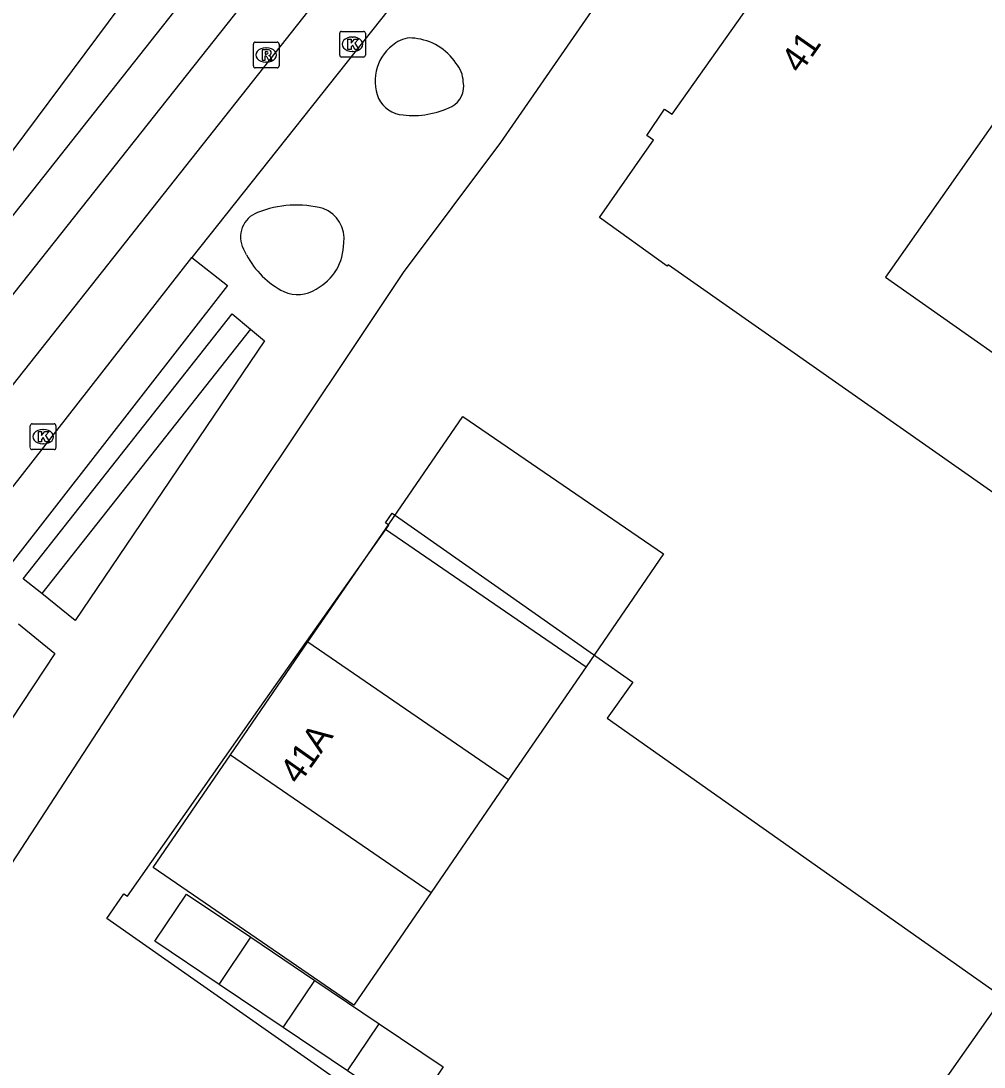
# Model space of a CAD drawing. Extents: x 161355 to 162026, y 386504 to 387459.
# Drawn here: x 161708.95 to 161746.37, y 387026.14 to 387066.79 of the extents above; entities that cross this region are included whole.
import ezdxf

# ---------------------------------------------------------------- set-up
doc = ezdxf.new("R2010")
doc.units = 0
for name, color, linetype in [('IMGEO_Groenvoorziening', 7, 'Continuous'), ('IMGEO_Kolk', 7, 'Continuous'), ('IMGEO_Pand', 7, 'Continuous'), ('IMGEO_Pand_nummerreeks', 7, 'Continuous'), ('IMGEO_Pand_vergunning_verleend', 7, 'Continuous'), ('IMGEO_Rijbaan_lokaal_open', 7, 'Continuous'), ('IMGEO_Rioolput', 7, 'Continuous'), ('IMGEO_Voetpad_open', 7, 'Continuous')]:
    doc.layers.add(name, color=color, linetype=linetype)

msp = doc.modelspace()

# ---------------------------------------------------------------- linework, layer by layer
at = {"layer": 'IMGEO_Groenvoorziening'}
msp.add_lwpolyline([(161717.868, 387054.816), (161709.757, 387044.533)], dxfattribs=at)
at = {"layer": 'IMGEO_Kolk'}
for p, q in [((161721.333, 387065.455), (161721.333, 387066.307)), ((161721.408, 387066.381), (161722.26, 387066.381)), ((161721.821, 387066.161), (161721.846, 387066.161)), ((161722.334, 387066.307), (161722.334, 387065.455)), ((161722.26, 387065.381), (161721.408, 387065.381)), ((161721.844, 387065.601), (161721.819, 387065.601)), ((161709.31, 387050.206), (161709.31, 387051.058)), ((161709.385, 387051.132), (161710.237, 387051.132)), ((161710.311, 387051.058), (161710.311, 387050.206)), ((161709.798, 387050.912), (161709.823, 387050.912)), ((161709.821, 387050.352), (161709.796, 387050.352)), ((161710.237, 387050.132), (161709.385, 387050.132))]:
    msp.add_line(p, q, dxfattribs=at)
for points in [[(161721.333, 387065.455), (161721.333, 387066.307)], [(161721.408, 387066.381), (161722.26, 387066.381)], [(161721.654, 387066.081), (161721.777, 387066.081), (161721.777, 387065.93), (161721.907, 387066.081), (161722.071, 387066.081), (161721.925, 387065.93), (161722.078, 387065.681), (161721.926, 387065.681), (161721.841, 387065.845), (161721.777, 387065.778), (161721.777, 387065.681), (161721.654, 387065.681), (161721.654, 387066.081)], [(161722.334, 387066.307), (161722.334, 387065.455)], [(161722.26, 387065.381), (161721.408, 387065.381)], [(161709.31, 387050.206), (161709.31, 387051.058)], [(161709.385, 387051.132), (161710.237, 387051.132)], [(161710.311, 387051.058), (161710.311, 387050.206)], [(161709.631, 387050.832), (161709.754, 387050.832), (161709.754, 387050.681), (161709.884, 387050.832), (161710.048, 387050.832), (161709.902, 387050.681), (161710.055, 387050.432), (161709.903, 387050.432), (161709.818, 387050.596), (161709.754, 387050.529), (161709.754, 387050.432), (161709.631, 387050.432), (161709.631, 387050.832)], [(161710.237, 387050.132), (161709.385, 387050.132)]]:
    msp.add_lwpolyline(points, dxfattribs=at)
for centre, start, end in [((161721.41, 387066.305), 91.552, 178.448), ((161721.41, 387066.305), 91.552, 178.448), ((161722.258, 387066.305), 1.552, 88.448), ((161722.258, 387066.305), 1.552, 88.448), ((161721.41, 387065.457), 181.552, 268.448), ((161721.41, 387065.457), 181.552, 268.448), ((161722.258, 387065.457), 271.552, 358.448), ((161722.258, 387065.457), 271.552, 358.448), ((161709.387, 387051.056), 91.552, 178.448), ((161709.387, 387051.056), 91.552, 178.448), ((161710.235, 387051.056), 1.552, 88.448), ((161710.235, 387051.056), 1.552, 88.448), ((161709.387, 387050.208), 181.552, 268.448), ((161709.387, 387050.208), 181.552, 268.448), ((161710.235, 387050.208), 271.552, 358.448), ((161710.235, 387050.208), 271.552, 358.448)]:
    msp.add_arc(centre, 0.0765, start, end, dxfattribs=at)
for centre, major_axis, ratio, start_param, end_param in [((161721.82, 387065.881), (-0.387, 0.002), 0.722429, 4.712389, 7.853982), ((161721.845, 387065.881), (-0.39, 0.002), 0.717154, 1.570796, 4.712389), ((161709.797, 387050.632), (-0.387, 0.002), 0.722429, 4.712389, 7.853982), ((161709.822, 387050.632), (-0.39, 0.002), 0.717154, 1.570796, 4.712389)]:
    msp.add_ellipse(centre, major_axis=major_axis, ratio=ratio, start_param=start_param, end_param=end_param, dxfattribs=at)
at = {"layer": 'IMGEO_Pand'}
for points in [[(161742.536, 387056.832), (161750.161, 387051.472), (161747.61, 387047.833), (161734.092, 387057.308), (161734.057, 387057.259), (161731.426, 387059.156), (161733.191, 387061.675), (161733.523, 387062.15), (161733.262, 387062.341), (161733.955, 387063.365), (161734.253, 387063.164), (161740.823, 387072.453), (161741.016, 387072.709), (161740.154, 387073.364), (161742.685, 387077.069), (161745.977, 387074.713), (161744.867, 387073.137), (161750.972, 387068.851), (161742.536, 387056.832)], [(161734.763, 387011.311), (161731.75, 387013.443), (161719.086, 387022.38), (161721.337, 387025.559), (161712.281, 387031.913), (161712.953, 387032.874), (161713.084, 387032.783), (161718.246, 387040.124), (161723.239, 387047.192), (161723.109, 387047.286), (161723.368, 387047.663), (161727.968, 387044.436), (161732.719, 387041.098), (161731.725, 387039.693), (161747.097, 387028.852), (161734.763, 387011.311)]]:
    msp.add_lwpolyline(points, dxfattribs=at)
at = {"layer": 'IMGEO_Pand_vergunning_verleend'}
for points in [[(161723.109, 387047.04), (161726.116, 387051.423), (161733.912, 387046.075), (161730.905, 387041.692)], [(161720.102, 387042.657), (161723.109, 387047.04)], [(161723.109, 387047.04), (161730.905, 387041.692)], [(161717.095, 387038.274), (161720.102, 387042.657)], [(161720.102, 387042.657), (161727.898, 387037.309)], [(161730.905, 387041.692), (161727.898, 387037.309)], [(161724.892, 387032.926), (161721.885, 387028.543), (161714.088, 387033.891), (161717.095, 387038.274)], [(161717.095, 387038.274), (161724.892, 387032.926)], [(161727.898, 387037.309), (161724.892, 387032.926)], [(161716.647, 387029.349), (161714.154, 387031.027), (161715.384, 387032.856), (161717.878, 387031.179)], [(161716.647, 387029.349), (161717.878, 387031.179)], [(161717.878, 387031.179), (161720.371, 387029.502)], [(161719.141, 387027.672), (161720.371, 387029.502)], [(161720.371, 387029.502), (161722.865, 387027.824)], [(161719.141, 387027.672), (161716.647, 387029.349)], [(161721.635, 387025.995), (161719.141, 387027.672)], [(161721.635, 387025.995), (161722.865, 387027.824)], [(161722.865, 387027.824), (161725.359, 387026.147), (161724.128, 387024.318), (161721.635, 387025.995)]]:
    msp.add_lwpolyline(points, dxfattribs=at)
at = {"layer": 'IMGEO_Rijbaan_lokaal_open'}
for points in [[(161690.719, 387036.239), (161693.118, 387039.45), (161698.781, 387046.763), (161740.72, 387099.817)], [(161690.719, 387036.239), (161692.257, 387035.086), (161694.354, 387037.936), (161700.184, 387045.485), (161742.263, 387098.632), (161740.72, 387099.817)], [(161698.235, 387039.499), (161743.949, 387097.333), (161745.465, 387096.127)], [(161713.744, 387068.636), (161706.773, 387059.283)], [(161723.911, 387068.099), (161715.591, 387057.592)], [(161697.086, 387033.89), (161715.591, 387057.592)]]:
    msp.add_lwpolyline(points, dxfattribs=at)
at = {"layer": 'IMGEO_Rioolput'}
for p, q in [((161717.979, 387065.038), (161717.979, 387065.89)), ((161718.054, 387065.964), (161718.906, 387065.964)), ((161718.467, 387065.744), (161718.492, 387065.744)), ((161718.98, 387065.89), (161718.98, 387065.038)), ((161718.906, 387064.964), (161718.054, 387064.964)), ((161718.49, 387065.184), (161718.465, 387065.184))]:
    msp.add_line(p, q, dxfattribs=at)
for points in [[(161717.979, 387065.038), (161717.979, 387065.89)], [(161718.054, 387065.964), (161718.906, 387065.964)], [(161718.568, 387065.662), (161718.316, 387065.664), (161718.316, 387065.264)], [(161718.98, 387065.89), (161718.98, 387065.038)], [(161718.316, 387065.264), (161718.44, 387065.264), (161718.44, 387065.426), (161718.451, 387065.426)], [(161718.494, 387065.583), (161718.44, 387065.583), (161718.44, 387065.502)], [(161718.44, 387065.502), (161718.492, 387065.502)], [(161718.498, 387065.397), (161718.569, 387065.264), (161718.709, 387065.264), (161718.644, 387065.39)], [(161718.906, 387064.964), (161718.054, 387064.964)]]:
    msp.add_lwpolyline(points, dxfattribs=at)
for centre, radius, start, end in [((161718.056, 387065.888), 0.0765, 91.552, 178.448), ((161718.056, 387065.888), 0.0765, 91.552, 178.448), ((161718.567, 387065.552), 0.109, 350.3612, 89.416), ((161718.904, 387065.888), 0.0765, 1.552, 88.448), ((161718.904, 387065.888), 0.0765, 1.552, 88.448), ((161718.45, 387065.373), 0.0533, 26.0293, 88.6989), ((161718.476, 387065.691), 0.19, 274.7715, 282.9687), ((161718.5, 387065.487), 0.0964, 77.0061, 93.1865), ((161718.514, 387065.544), 0.0378, 276.6634, 79.6772), ((161718.565, 387065.552), 0.112, 277.5842, 350.9817), ((161718.549, 387065.337), 0.108, 29.5134, 73.7905), ((161718.056, 387065.04), 0.0765, 181.552, 268.448), ((161718.056, 387065.04), 0.0765, 181.552, 268.448), ((161718.904, 387065.04), 0.0765, 271.552, 358.448), ((161718.904, 387065.04), 0.0765, 271.552, 358.448)]:
    msp.add_arc(centre, radius, start, end, dxfattribs=at)
for centre, major_axis, ratio, start_param, end_param in [((161718.466, 387065.464), (-0.387, 0.002), 0.722429, 4.712389, 7.853982), ((161718.491, 387065.464), (-0.39, 0.002), 0.717154, 1.570796, 4.712389)]:
    msp.add_ellipse(centre, major_axis=major_axis, ratio=ratio, start_param=start_param, end_param=end_param, dxfattribs=at)
at = {"layer": 'IMGEO_Voetpad_open'}
for points in [[(161677.419, 386973.992), (161689.028, 387000), (161692.864, 387007.756), (161695.643, 387012.888), (161703.036, 387025.535), (161713.413, 387041.445), (161718.884, 387049.626), (161718.954, 387049.732), (161722.833, 387055.531), (161723.819, 387057.006), (161727.598, 387062.069), (161735.832, 387073.978), (161748.817, 387090.782)], [(161715.591, 387057.592), (161716.972, 387056.513), (161698.537, 387032.824), (161697.086, 387033.89)], [(161717.716, 387057.701), (161717.593, 387057.93)], [(161709.757, 387044.533), (161709.043, 387045.106), (161717.158, 387055.41), (161717.868, 387054.816)], [(161717.868, 387054.816), (161718.411, 387054.361), (161711.062, 387043.488), (161709.757, 387044.533)], [(161708.856, 387043.363), (161710.272, 387042.21), (161706.431, 387036.413), (161702.643, 387030.648), (161700.424, 387032.231)]]:
    msp.add_lwpolyline(points, dxfattribs=at)
for centre, radius, start, end in [((161724.096, 387065.15), 0.976, 80.902, 126.8789), ((161724.019, 387063.918), 2.208, 33.8864, 83.9864), ((161724.473, 387064.451), 1.766, 123.0427, 202.4644), ((161724.964, 387064.388), 1.17, 1.5208, 40.5858), ((161725.272, 387064.236), 0.88, 297.9971, 11.9691), ((161723.878, 387064.287), 1.156, 206.2182, 265.8484), ((161724.179, 387066.555), 3.443, 263.5725, 295.9314), ((161719.647, 387055.662), 3.974, 74.6863, 112.2569), ((161718.483, 387058.395), 1.004, 109.8455, 207.6064), ((161720.277, 387058.343), 1.226, 351.4107, 69.9471), ((161719.479, 387058.147), 2.01, 297.8251, 0.3698), ((161720.64, 387059.214), 3.292, 207.3533, 243.4414), ((161719.703, 387057.44), 1.287, 245.4454, 303.7097)]:
    msp.add_arc(centre, radius, start, end, dxfattribs=at)

# ---------------------------------------------------------------- texts
at = {"layer": 'IMGEO_Pand_nummerreeks'}
for s, rotation, p in [('41', 54.9753, (161739.225, 387064.699)), ('41A', 54.7175, (161719.745, 387037.07))]:
    msp.add_text(s, height=1, rotation=rotation, dxfattribs=at).set_placement(p)

doc.saveas('drawing.dxf')
